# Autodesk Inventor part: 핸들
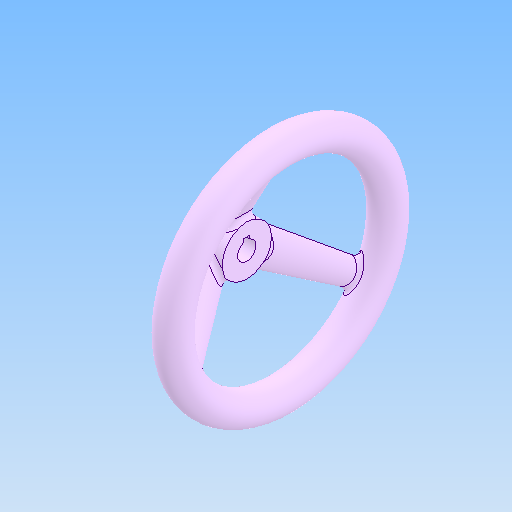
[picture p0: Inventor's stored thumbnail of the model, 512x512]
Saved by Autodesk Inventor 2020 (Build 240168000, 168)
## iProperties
Created: 2024-07
Part Number: 핸들
Material: 강철, 연강
Document SubType Name: Modeling
Designer: oem
Density: 7.85 g/cm^3
Appearance: 기본값
Author: jhkim
Sending System: Autodesk Inventor 2025
Preprocessor: ST-DEVELOPER v20
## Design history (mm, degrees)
feature "솔리드1"
node "솔리드2"
